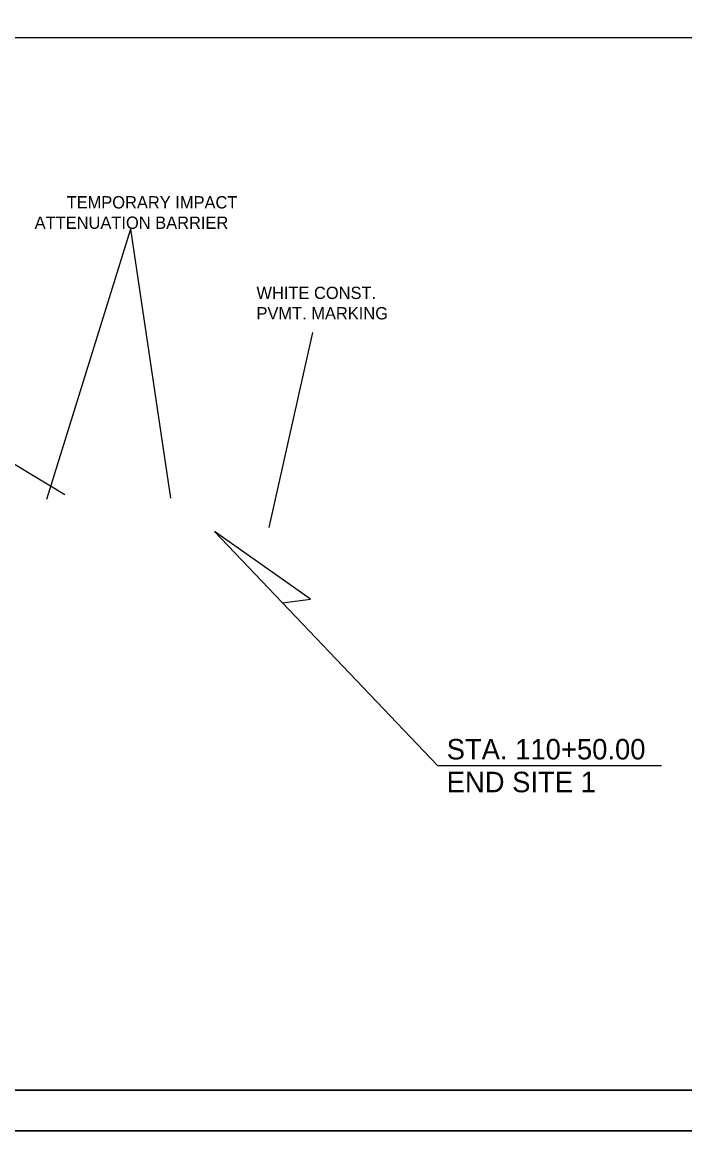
# Model space of a CAD drawing. Extents: x 1398460 to 1408037, y 380768 to 383968.
# Drawn here: x 1401509 to 1401833, y 381834 to 382375 of the extents above; entities that cross this region are included whole.
import ezdxf

# ---------------------------------------------------------------- set-up
doc = ezdxf.new("R2010")
doc.units = 0
for name, color, linetype in [('Default', 7, 'Continuous'), ('MOT STAGE ALL', 7, 'Continuous'), ('R_Border', 7, 'Continuous'), ('R_Dimension', 7, 'Continuous'), ('R_MOT', 7, 'Continuous'), ('R_No Plot', 7, 'Continuous')]:
    doc.layers.add(name, color=color, linetype=linetype)

msp = doc.modelspace()

# ---------------------------------------------------------------- linework, layer by layer
at = {"layer": 'Default'}
for p, q in [((1401603.27, 382126.66), (1401712.07, 382012.49)), ((1401712.07, 382012.49), (1401821.35, 382012.49))]:
    msp.add_line(p, q, dxfattribs=at)
msp.add_lwpolyline([(1401636.5, 382091.79), (1401650.12, 382093.66), (1401603.27, 382126.66)], dxfattribs=at)
at = {"layer": 'R_Border'}
for p, q in [((1400727.57, 382367.77), (1402308.47, 382367.77)), ((1402308.47, 381854.12), (1400727.57, 381854.12))]:
    msp.add_line(p, q, dxfattribs=at)
at = {"layer": 'R_MOT'}
for p, q in [((1401562.31, 382274.11), (1401521.27, 382142.18)), ((1401562.31, 382274.11), (1401581.8, 382142.88)), ((1401651.03, 382223.73), (1401629.81, 382128.53)), ((1401530.15, 382144.56), (1401412.13, 382215.9))]:
    msp.add_line(p, q, dxfattribs=at)
at = {"layer": 'R_No Plot'}
msp.add_line((1400665.56, 381834.22), (1402332.23, 381834.22), dxfattribs=at)
for points in [[(1400665.53, 382900.89), (1402332.23, 382900.89), (1402332.23, 381834.2), (1400665.53, 381834.2)], [(1400727.57, 382881.42), (1400727.57, 381854.12), (1402308.47, 381854.12), (1402308.47, 382710.36), (1402191.82, 382710.36), (1402191.82, 382832.02), (1401995.27, 382832.02), (1401995.27, 382881.42)], [(1400727.57, 382881.42), (1400727.57, 382367.77), (1402308.47, 382367.77), (1402308.47, 382710.36), (1402191.82, 382710.36), (1402191.82, 382832.02), (1401995.27, 382832.02), (1401995.27, 382881.42)], [(1401897.17, 382881.42), (1401995.27, 382881.42), (1401995.27, 382832.02), (1402075.83, 382832.02), (1402191.82, 382832.02), (1402191.82, 382710.36), (1402308.47, 382710.36), (1402308.47, 381854.12), (1400727.57, 381854.12), (1400727.57, 382881.42)], [(1400727.57, 381854.12), (1400727.57, 382367.77), (1402308.47, 382367.77), (1402308.47, 381854.12)]]:
    msp.add_lwpolyline(points, close=True, dxfattribs=at)

# ---------------------------------------------------------------- texts
at = {"layer": 'MOT STAGE ALL'}
for s, rotation, p in [('TEMPORARY IMPACT', 0, (1401531.05, 382284.28)), (' ATTENUATION BARRIER', 0, (1401513.24, 382274.32)), ('WHITE CONST.', 360, (1401623.72, 382240.09)), ('PVMT. MARKING', 360, (1401623.72, 382230.13))]:
    msp.add_text(s, height=6.0001, rotation=rotation, dxfattribs=at).set_placement(p)
at = {"layer": 'R_Dimension'}
for s, p in [('STA. 110+50.00', (1401716.55, 382015.41)), ('END SITE 1', (1401716.55, 381999.41))]:
    msp.add_text(s, height=10, dxfattribs=at).set_placement(p)

doc.saveas('drawing.dxf')
